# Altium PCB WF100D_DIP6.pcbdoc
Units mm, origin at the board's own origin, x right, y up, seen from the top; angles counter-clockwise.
Board outline 21.26 x 24.55 mm, 2 copper layers (Top Layer, Bottom Layer); 1 components, 0 nets, 6 pads, 0 vias.
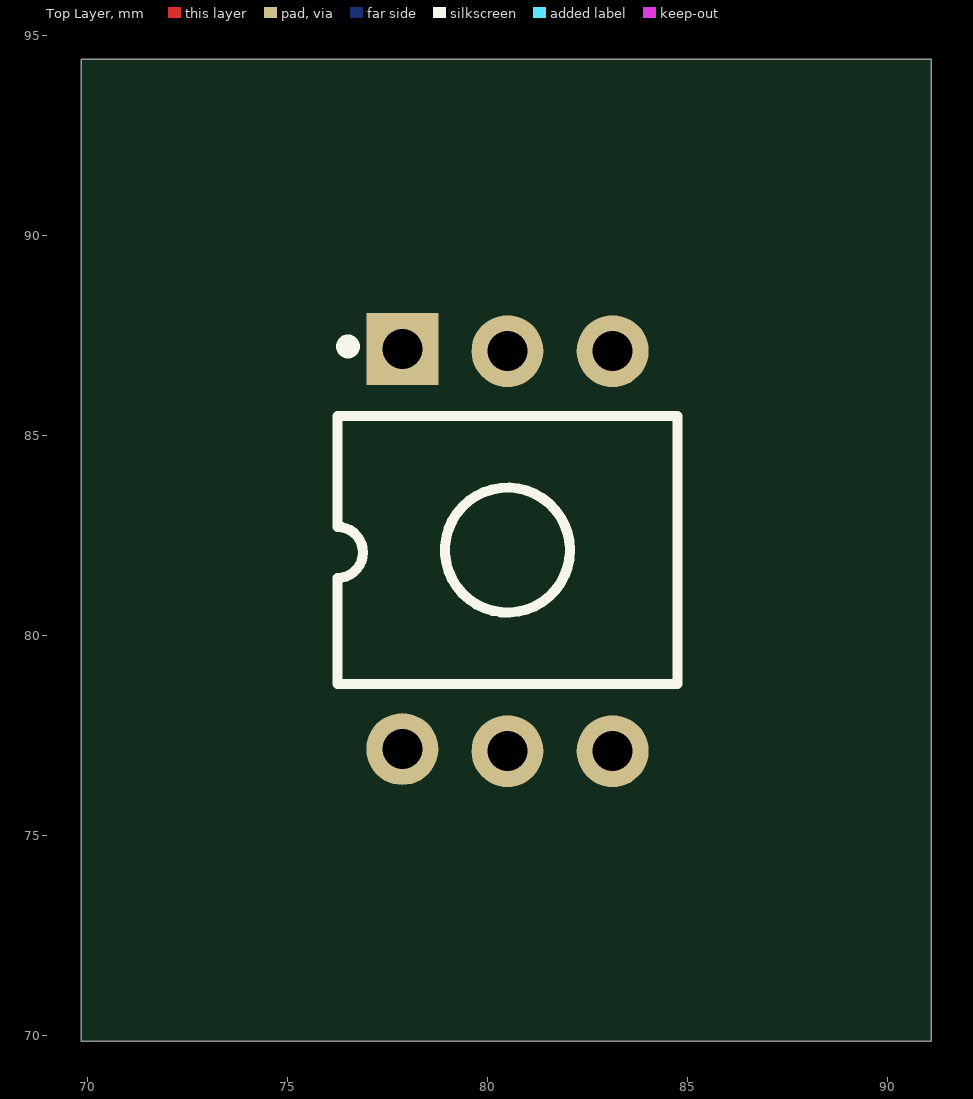
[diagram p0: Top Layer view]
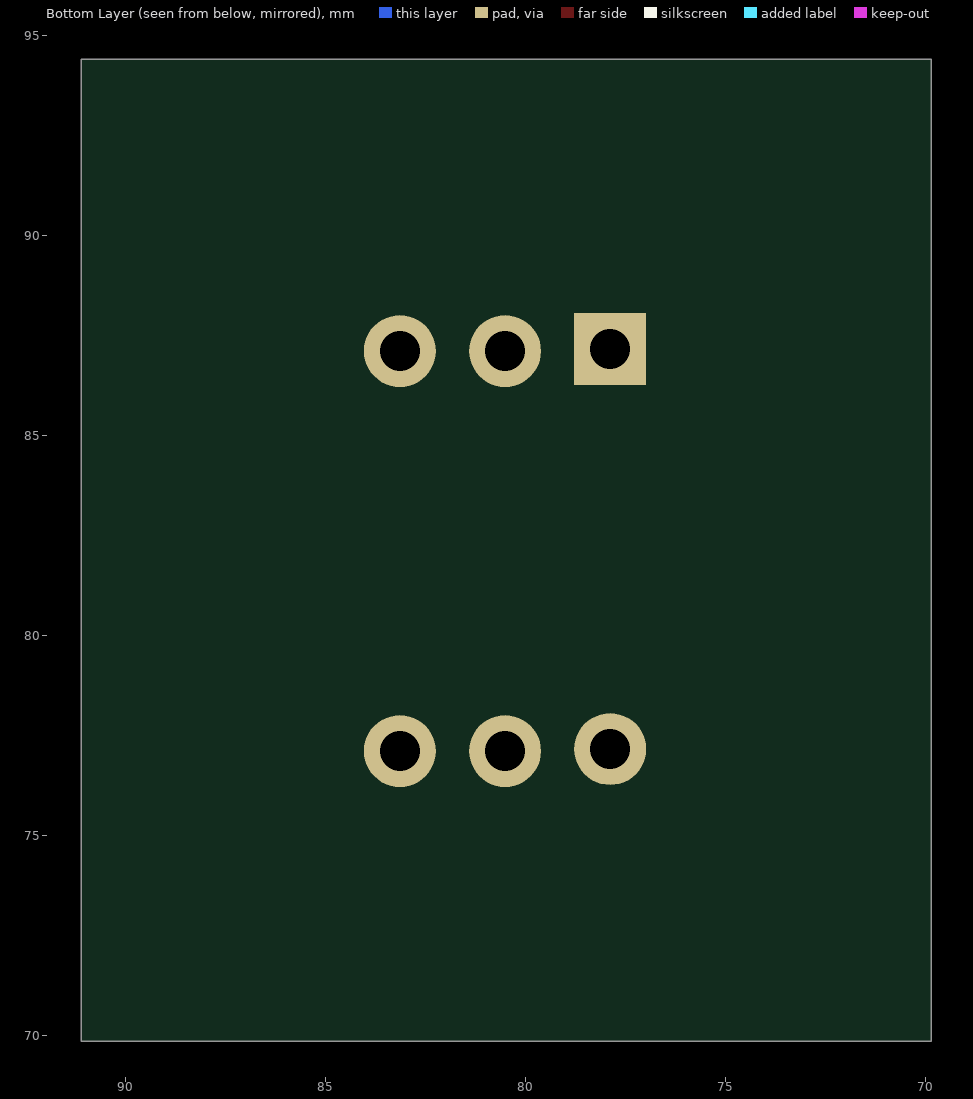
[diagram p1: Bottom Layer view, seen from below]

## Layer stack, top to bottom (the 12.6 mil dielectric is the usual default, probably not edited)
Top Solder: solder mask 0.0102, Solder Resist, Dk 3.5
Top Layer: signal copper 0.0356
Dielectric 1: dielectric 0.32, FR-4, Dk 4.8
Bottom Layer: signal copper 0.0356
Bottom Solder: solder mask 0.0102, Solder Resist, Dk 3.5

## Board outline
91.11,69.85 69.85,69.85 69.85,94.401 91.11,94.401

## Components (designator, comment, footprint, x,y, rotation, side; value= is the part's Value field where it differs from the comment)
? "DIP-6_L8.5-W7.5-P2.63-LS10.0-TL" DIP-6_L8.5-W7.5-P2.63-LS10.0-TL 80.51,82.125 r0 top

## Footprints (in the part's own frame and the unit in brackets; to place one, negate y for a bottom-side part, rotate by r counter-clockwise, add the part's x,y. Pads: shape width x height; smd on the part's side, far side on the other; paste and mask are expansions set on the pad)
DIP-6_L8.5-W7.5-P2.63-LS10.0-TL [mm]
  rect 1.8x1.8 hole 1: 1(-2.63,5.025)
  round 1.8 hole 1: 2(0,4.975) 3(2.63,4.975) 4(2.63,-5.025) 5(0,-5.025) 6(-2.63,-4.975)
  silkscreen extent -4.25,-3.35 4.25,5.24

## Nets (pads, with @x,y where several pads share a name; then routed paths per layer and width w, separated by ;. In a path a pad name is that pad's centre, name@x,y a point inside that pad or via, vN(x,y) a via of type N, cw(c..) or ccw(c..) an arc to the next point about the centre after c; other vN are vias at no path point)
pads on no net: ?.1 ?.2 ?.3 ?.4 ?.5 ?.6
